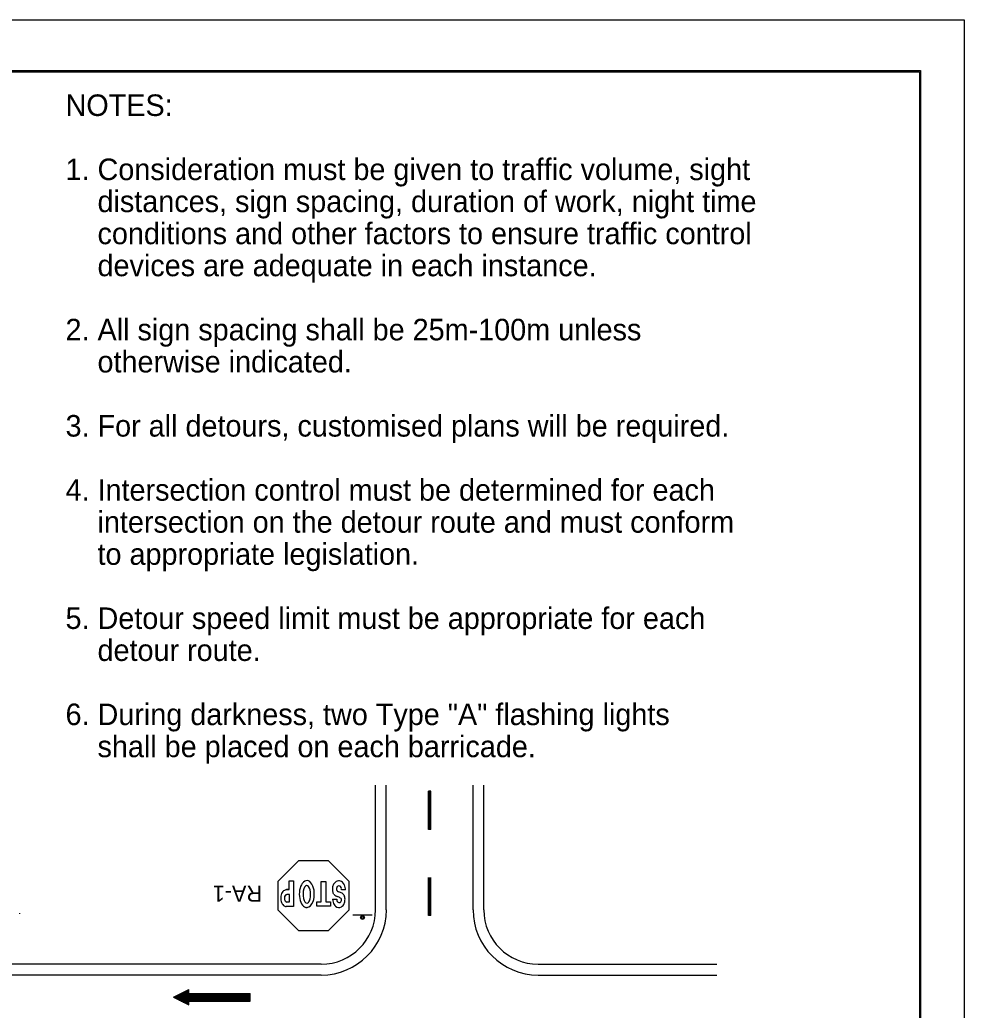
# Model space of a CAD drawing. Extents: x 1482 to 1692, y 225 to 494.
# Drawn here: x 1587.1 to 1692.4, y 383.2 to 493.6 of the extents above; entities that cross this region are included whole.
import ezdxf

# ---------------------------------------------------------------- set-up
doc = ezdxf.new("R2010")
doc.units = 0
for name, color, linetype in [('Level 1', 7, 'Continuous'), ('Level 17', 7, 'Continuous'), ('Level 2', 7, 'Continuous'), ('Level 60', 7, 'Continuous')]:
    doc.layers.add(name, color=color, linetype=linetype)

msp = doc.modelspace()

# ---------------------------------------------------------------- linework, layer by layer
at = {"layer": 'Level 17'}
for p, q in [((1617.12, 396.63), (1617.12, 397.61)), ((1617.12, 397.61), (1617.59, 397.61)), ((1617.59, 397.61), (1617.59, 394.74)), ((1617.12, 396.63), (1616.82, 396.63)), ((1616.83, 396.63), (1617.12, 396.63)), ((1620.7, 397.53), (1621.2, 397.53)), ((1620.7, 395.28), (1620.7, 397.53)), ((1621.2, 397.53), (1621.2, 395.27)), ((1623.42, 396.6), (1622.97, 396.6)), ((1623.28, 397.17), (1623.28, 397.17)), ((1617.17, 396.09), (1616.87, 396.09)), ((1617.17, 396.09), (1616.87, 396.09)), ((1617.17, 395.26), (1617.17, 396.09)), ((1617.17, 395.26), (1617.17, 396.09)), ((1621.96, 395.57), (1622.45, 395.57)), ((1617.59, 394.74), (1616.79, 394.74)), ((1616.86, 395.26), (1617.17, 395.26)), ((1616.86, 395.26), (1617.17, 395.26)), ((1619.12, 394.64), (1619.11, 394.64)), ((1619.14, 395.13), (1619.12, 395.12)), ((1620.2, 394.77), (1620.2, 395.28)), ((1620.2, 395.28), (1620.7, 395.28)), ((1621.73, 394.77), (1620.2, 394.77)), ((1621.2, 395.27), (1621.73, 395.27)), ((1621.73, 395.27), (1621.73, 394.77)), ((1626.37, 393.77), (1624.24, 393.77))]:
    msp.add_line(p, q, dxfattribs=at)
msp.add_lwpolyline([(1615.9, 397.59), (1618.2, 399.89), (1621.46, 399.89), (1623.76, 397.59), (1623.76, 394.33), (1621.46, 392.04), (1618.2, 392.04), (1615.9, 394.33)], close=True, dxfattribs=at)
msp.add_lwpolyline([(1587.08, 393.92), (1587.08, 394.02)], dxfattribs=at)
for radius in [0.213, 0.107]:
    msp.add_circle((1625.3, 393.53), radius, dxfattribs=at)
for centre, radius, start, end in [((1622.78, 396.87), 0.782, 113.1413, 144.9906), ((1622.67, 397.14), 0.489, 52.0536, 112.7397), ((1616.8, 396.12), 0.478, 115.3838, 142.6188), ((1616.94, 395.94), 0.706, 106.602, 119.8091), ((1616.8, 396.46), 0.166, 79.7909, 113.5419), ((1623.67, 396.67), 1.73, 171.247, 183.9864), ((1623.16, 396.67), 1.22, 185.9097, 201.9865), ((1623.26, 396.55), 1.36, 145.5092, 163.2894), ((1622.82, 396.74), 0.413, 146.253, 178.7323), ((1622.72, 396.7), 0.319, 172.5761, 210.4776), ((1622.73, 396.73), 0.348, 214.2083, 254.1552), ((1622.68, 396.73), 0.31, 95.4374, 134.0626), ((1622.66, 396.71), 0.335, 50.6966, 91.4573), ((1622.61, 396.74), 0.344, 6.8728, 42.7449), ((1622.29, 396.61), 0.685, 359.0172, 13.5172), ((1622.33, 396.66), 1.07, 28.4154, 53.6553), ((1621.92, 396.53), 1.5, 2.3841, 24.9519), ((1617.39, 395.69), 1.21, 169.7521, 182.7916), ((1617.39, 395.69), 1.21, 169.7521, 182.7916), ((1617.69, 395.72), 1.51, 183.3903, 195.6597), ((1617.75, 395.6), 1.59, 158.3153, 168.6699), ((1617, 395.9), 0.774, 138.2922, 158.6031), ((1617, 395.9), 0.774, 138.2922, 158.6031), ((1617.06, 395.67), 0.468, 170.3417, 195.2342), ((1617.06, 395.67), 0.468, 170.3417, 195.2342), ((1617.01, 395.73), 0.418, 146.5086, 177.0313), ((1617.01, 395.73), 0.418, 146.5086, 177.0313), ((1617.04, 395.61), 0.44, 188.6031, 214.217), ((1617.04, 395.61), 0.44, 188.6031, 214.217), ((1616.93, 395.77), 0.325, 101.9191, 145.7868), ((1616.93, 395.77), 0.325, 101.9191, 145.7868), ((1616.91, 395.53), 0.283, 215.1198, 259.3117), ((1616.91, 395.53), 0.283, 215.1198, 259.3117), ((1623.21, 395.59), 1.24, 180.6952, 197.1452), ((1620.54, 394.79), 2.05, 39.479, 43.426), ((1622.95, 396.94), 1.17, 226.2465, 247.9263), ((1622.84, 395.51), 0.405, 170.4412, 219.3244), ((1621.96, 394.26), 1.68, 57.9816, 70.979), ((1620.65, 391.25), 5.52, 64.4624, 68.8312), ((1622.69, 395.44), 0.264, 293.8064, 352.2407), ((1622.72, 395.48), 0.242, 344.131, 58.1476), ((1622.6, 395.6), 0.762, 20.4481, 55.1107), ((1622.13, 395.54), 1.22, 337.7332, 357.1392), ((1622.28, 395.57), 1.07, 354.8171, 15.9183), ((1616.99, 395.49), 0.778, 193.0674, 213.762), ((1616.98, 395.42), 0.732, 209.2241, 228.5308), ((1616.98, 395.42), 0.732, 209.2241, 228.5308), ((1616.83, 395.21), 0.477, 224.8528, 265.0441), ((1622.89, 395.45), 0.898, 194.564, 229.0063), ((1622.67, 395.16), 0.532, 226.1369, 301.3987), ((1622.71, 395.46), 0.277, 227.3017, 289.0119), ((1622.47, 395.43), 0.87, 303.3662, 335.6734)]:
    msp.add_arc(centre, radius, start, end, dxfattribs=at)
for centre, major_axis, ratio, start_param, end_param in [((1619.09, 396.14), (0.01, 1.5), 0.558644, 4.129576, 6.939747), ((1619.09, 396.14), (0.01, 1.5), 0.558644, 0.656861, 3.168126), ((1619.09, 396.1), (-0.005, 0.977), 0.432619, 0.881967, 3.190734), ((1619.09, 396.1), (-0.005, 0.977), 0.432619, 3.890436, 7.165085), ((1619.09, 396.1), (-0.005, 0.977), 0.432619, 3.239639, 3.888884), ((1619.09, 396.14), (0.01, 1.5), 0.558644, 3.185857, 4.129398)]:
    msp.add_ellipse(centre, major_axis=major_axis, ratio=ratio, start_param=start_param, end_param=end_param, dxfattribs=at)
at = {"layer": 'Level 2'}
for p, q in [((1626.75, 394.37), (1626.75, 408.27)), ((1627.95, 394.37), (1627.95, 408.27)), ((1632.66, 403.34), (1632.66, 407.61)), ((1632.92, 407.61), (1632.66, 407.61)), ((1632.73, 403.34), (1632.73, 407.61)), ((1632.79, 403.34), (1632.79, 407.61)), ((1632.86, 403.34), (1632.86, 407.61)), ((1632.92, 403.34), (1632.92, 407.61)), ((1637.63, 394.37), (1637.63, 408.27)), ((1638.84, 394.37), (1638.84, 408.27)), ((1632.92, 403.34), (1632.66, 403.34)), ((1632.66, 393.73), (1632.66, 398)), ((1632.73, 393.73), (1632.73, 398)), ((1632.79, 393.73), (1632.79, 398)), ((1632.86, 393.73), (1632.86, 398)), ((1632.92, 393.73), (1632.92, 398)), ((1632.92, 393.73), (1632.66, 393.73)), ((1620.7, 388.32), (1559.23, 388.32)), ((1644.89, 388.32), (1664.83, 388.32)), ((1620.7, 387.11), (1559.23, 387.11)), ((1644.89, 387.11), (1664.83, 387.11)), ((1604.23, 384.64), (1605.93, 385.49)), ((1605.93, 385.06), (1605.93, 385.49)), ((1604.23, 384.64), (1612.76, 384.64)), ((1604.23, 384.64), (1605.93, 383.78)), ((1604.44, 384.74), (1612.76, 384.74)), ((1604.44, 384.53), (1612.76, 384.53)), ((1604.65, 384.85), (1612.76, 384.85)), ((1604.65, 384.42), (1612.76, 384.42)), ((1604.87, 384.96), (1612.76, 384.96)), ((1604.87, 384.32), (1612.76, 384.32)), ((1605.08, 385.06), (1612.76, 385.06)), ((1605.3, 385.17), (1605.93, 385.17)), ((1605.51, 385.28), (1605.93, 385.28)), ((1605.72, 385.38), (1605.93, 385.38)), ((1605.93, 385.06), (1612.76, 385.06)), ((1612.76, 384.21), (1612.76, 385.06)), ((1605.08, 384.21), (1612.76, 384.21)), ((1605.3, 384.1), (1605.93, 384.1)), ((1605.51, 384), (1605.93, 384)), ((1605.72, 383.89), (1605.93, 383.89)), ((1605.93, 384.21), (1612.76, 384.21)), ((1605.93, 383.78), (1605.93, 384.21))]:
    msp.add_line(p, q, dxfattribs=at)
for centre, radius, start, end in [((1620.7, 394.37), 7.26, 270, 360), ((1620.7, 394.37), 6.05, 270, 360), ((1644.89, 394.37), 7.26, 180, 270), ((1644.89, 394.37), 6.05, 180, 270)]:
    msp.add_arc(centre, radius, start, end, dxfattribs=at)
at = {"layer": 'Level 60'}
for points in [[(1482.41, 493.62), (1692.41, 493.62), (1692.41, 224.63), (1482.41, 224.63)], [(1493.13, 487.96), (1687.52, 487.96), (1687.52, 230.21), (1493.13, 230.21)], [(1500.54, 487.82), (1687.41, 487.82), (1687.41, 230.44), (1500.54, 230.44)]]:
    msp.add_lwpolyline(points, close=True, dxfattribs=at)

# ---------------------------------------------------------------- texts
at = {"layer": 'Level 1'}
for s, p in [('NOTES:', (1592.18, 482.9)), ('1. Consideration must be given to traffic volume, sight ', (1592.18, 475.75)), ('    distances, sign spacing, duration of work, night time ', (1592.18, 472.18)), ('    conditions and other factors to ensure traffic control ', (1592.18, 468.6)), ('    devices are adequate in each instance.', (1592.18, 465.03)), ('2. All sign spacing shall be 25m-100m unless', (1592.18, 457.88)), ('    otherwise indicated.', (1592.18, 454.3)), ('3. For all detours, customised plans will be required.', (1592.18, 447.15)), ('4. Intersection control must be determined for each ', (1592.18, 440)), ('    intersection on the detour route and must conform ', (1592.18, 436.43)), ('    to appropriate legislation.', (1592.18, 432.85)), ('5. Detour speed limit must be appropriate for each ', (1592.18, 425.7)), ('    detour route.', (1592.18, 422.13)), ('6. During darkness, two Type "A" flashing lights', (1592.18, 414.98)), ('    shall be placed on each barricade.', (1592.18, 411.4))]:
    msp.add_text(s, height=2.4, dxfattribs=at).set_placement(p)
at = {"layer": 'Level 17'}
msp.add_text('RA-1', height=1.8, rotation=180, dxfattribs=at).set_placement((1614.09, 397.08))

doc.saveas('drawing.dxf')
